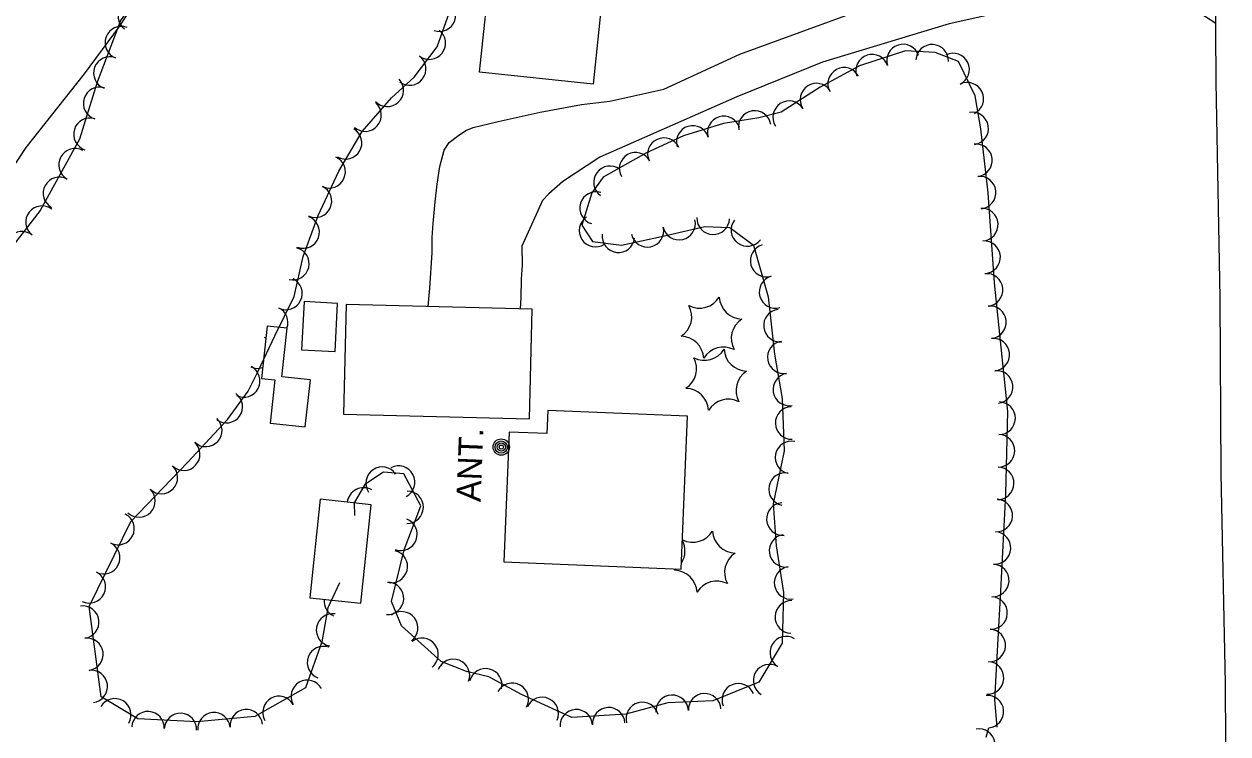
# Model space of a CAD drawing. Extents: x 296487 to 298842, y 31545 to 32791.
# Drawn here: x 297435.1 to 297732.5, y 31860.3 to 32035.7 of the extents above; entities that cross this region are included whole.
import ezdxf

# ---------------------------------------------------------------- set-up
doc = ezdxf.new("R2010")
doc.units = 0
for name, color, linetype in [('Level 11', 7, 'Continuous'), ('Level 12', 7, 'Continuous'), ('Level 14', 7, 'Continuous'), ('Level 17', 7, 'Continuous'), ('Level 18', 7, 'Continuous')]:
    doc.layers.add(name, color=color, linetype=linetype)

msp = doc.modelspace()

# ---------------------------------------------------------------- linework, layer by layer
at = {"layer": 'Level 11'}
msp.add_lwpolyline([(297732.45, 31749.54), (297732.24, 31791.84), (297732.13, 31829.29), (297731.83, 31872.75), (297730.81, 31924.68), (297730.53, 31968.01), (297729.53, 32021.42), (297729.12, 32084.97), (297728.52, 32147.82), (297727.87, 32212.59), (297727.19, 32277.97), (297726.38, 32352.97), (297725.93, 32414.91), (297724.99, 32486.15), (297724.55, 32554.59), (297723.53, 32621.52), (297723.38, 32689.57), (297722.58, 32747.62), (297722.25, 32760.6)], dxfattribs=at)
at = {"layer": 'Level 12'}
for points in [[(297547.6, 32023.83), (297550.48, 32050.93), (297578.49, 32047.96), (297575.62, 32020.86)], [(297512.53, 31966.69), (297504.25, 31967.13), (297503.62, 31955.23), (297511.9, 31954.79)], [(297560.58, 31965.29), (297514.62, 31966.43), (297513.95, 31939.3), (297559.91, 31938.16)], [(297505.79, 31947.78), (297498.77, 31948.53), (297500.06, 31960.54), (297495.1, 31961.07), (297493.71, 31948.12), (297496.98, 31947.77), (297495.84, 31937.1), (297504.54, 31936.17)], [(297553.6, 31902.79), (297597.41, 31901.02), (297598.94, 31938.83), (297564.47, 31940.22), (297564.23, 31934.5), (297554.9, 31934.87)], [(297520.83, 31916.93), (297508.24, 31918.27), (297505.64, 31893.94), (297518.23, 31892.59)]]:
    msp.add_lwpolyline(points, close=True, dxfattribs=at)
at = {"layer": 'Level 14'}
for centre, radius in [((297552.94, 31931.18), 2.02), ((297552.93, 31931.17), 1.52), ((297552.97, 31931.18), 1.01), ((297552.96, 31931.18), 0.502)]:
    msp.add_circle(centre, radius, dxfattribs=at)
at = {"layer": 'Level 17'}
for points in [[(297623.99, 32250.43), (297610.13, 32233.83), (297591.62, 32212.39), (297578.2, 32195.81), (297559.31, 32173.69), (297545.59, 32153.8), (297535.31, 32140.44), (297511.71, 32112.03), (297495.92, 32087.9), (297480.91, 32066.68), (297468.73, 32050.81), (297458.54, 32035.07), (297449.94, 32023.36), (297435.5, 32005.16), (297419.75, 31981.41), (297405.85, 31956.85), (297394.34, 31937.67), (297382.2, 31916.55), (297361.04, 31874.71), (297352.86, 31857.17), (297348.71, 31848.4), (297345.52, 31842.04), (297344.4, 31839.03)], [(297729.44, 32035.81), (297724.4, 32039.11), (297721.87, 32040.79), (297718.97, 32042.8), (297715.9, 32043.7), (297713, 32044.12), (297711.06, 32044.15), (297709.77, 32044.05), (297688.43, 32041.23), (297663.57, 32035.71), (297632.32, 32026.27), (297611.12, 32017.74), (297577.29, 32002.8), (297568.14, 31996.83), (297564.66, 31993.74), (297563.14, 31992.11), (297558.04, 31980.8), (297558.08, 31976.14), (297557.89, 31972.64), (297557.78, 31968.11), (297557.58, 31965.36)], [(297534.93, 31965.92), (297535.29, 31970.41), (297535.84, 31979.17), (297535.88, 31982.92), (297536.12, 31986.45), (297536.64, 31991.78), (297537.15, 31996.11), (297537.77, 32000.47), (297538.86, 32004.55), (297540.07, 32006.43), (297542.11, 32008.03), (297544.23, 32009.37), (297545.98, 32010.17), (297552.18, 32011.64), (297562.58, 32013.89), (297572.81, 32015.8), (297579.78, 32016.64), (297593.08, 32019.57), (297611.92, 32028.26), (297648.67, 32041.76)]]:
    msp.add_lwpolyline(points, dxfattribs=at)
at = {"layer": 'Level 18'}
for points in [[(297625.12, 32240.7), (297616.41, 32235.22), (297611.15, 32232.85), (297605.92, 32227.61), (297598.25, 32212.26), (297590.54, 32195.59), (297580.41, 32181.49), (297570.67, 32169.45), (297556.76, 32152.58), (297535.87, 32128.56), (297522.19, 32111.09), (297509.57, 32094.44), (297500.55, 32082.07), (297485.94, 32065.55), (297469.04, 32050.05), (297458.99, 32036.76), (297453.15, 32021.32), (297448.73, 32007.23), (297439.07, 31989.61), (297427.97, 31975.39)], [(297512.96, 31897.65), (297510.08, 31891.48), (297508.63, 31883.02), (297504.56, 31871.72), (297492.07, 31864.64), (297477.75, 31863.3), (297463.19, 31864.07), (297454.13, 31869.44), (297451.14, 31891.8), (297461.48, 31912.76), (297475.44, 31927.33), (297485.34, 31937.98), (297490.43, 31945.03), (297492.93, 31949.9), (297496.98, 31958.65), (297501.75, 31968.41), (297504.04, 31978.23), (297507.72, 31988.36), (297512.81, 31999.32), (297518.6, 32009.17), (297525.86, 32017.44), (297531.42, 32022.57), (297537.12, 32030.07), (297541.1, 32041.21)], [(297675.48, 31862), (297674.9, 31868.74), (297675.39, 31877.8), (297676.34, 31895.69), (297677.63, 31919.54), (297678.07, 31939.98), (297674.78, 31971.76), (297673.23, 31993.97), (297671.43, 32009.79), (297670.05, 32018), (297665.92, 32026.48), (297660.15, 32028.7), (297652.8, 32029.09), (297641.45, 32025.36), (297631.7, 32020.09), (297622.13, 32013.94), (297616.56, 32012.55), (297607.84, 32011.1), (297597.97, 32008.07), (297588.79, 32003.87), (297578.14, 31997.89), (297575.31, 31994.01), (297572.88, 31985.97), (297575.5, 31981.96), (297582.67, 31981.07), (297592.54, 31983.23), (297603.21, 31985.69), (297609.43, 31985.46), (297615.23, 31981.07), (297618.85, 31968.31), (297620.48, 31954.15), (297622.35, 31943.15), (297622.84, 31930.28), (297620.15, 31917.16), (297620.86, 31906.75), (297622.67, 31895.23), (297622.32, 31882.76), (297616.54, 31873.07), (297605.25, 31868.48), (297594.08, 31867.96), (297583.69, 31865.19), (297570.36, 31864.36), (297557.91, 31870.01), (297549.84, 31874.41), (297544.34, 31875.76), (297538.14, 31878.18), (297528.31, 31887.01), (297525.82, 31893.01), (297528.96, 31905.79), (297533.07, 31916.62), (297528.88, 31924.54), (297523.83, 31924.99), (297519.28, 31921.94), (297516.64, 31917.42), (297516.72, 31914.3)], [(297672.71, 31859.47), (297673.38, 31861.82)]]:
    msp.add_lwpolyline(points, dxfattribs=at)
for centre, radius, start, end in [((297462.31, 32037.69), 4.01, 52.906, 232.8907), ((297537.69, 32037.89), 4.01, 250.3652, 70.3499), ((297459.08, 32031.09), 4.01, 69.292, 249.2767), ((297535.17, 32030.97), 4.01, 232.7376, 52.7223), ((297652.21, 32026.68), 4.02, 18.1955, 198.1802), ((297659.4, 32026.63), 4.02, 356.922, 176.9067), ((297664.56, 32024.47), 4.02, 295.9288, 115.9135), ((297456.25, 32023.6), 4.01, 69.292, 249.2767), ((297530.32, 32024.59), 4.01, 232.7376, 52.7223), ((297644.57, 32024.17), 4.02, 18.1955, 198.1802), ((297637.66, 32020.92), 4.02, 28.4036, 208.3883), ((297453.71, 32016.12), 4.01, 72.5902, 252.5749), ((297524.8, 32019.32), 4.01, 222.7158, 42.7004), ((297630.82, 32017.03), 4.02, 32.7374, 212.7221), ((297668.08, 32017.24), 4.02, 295.9288, 115.9135), ((297624.06, 32012.68), 4.02, 32.7374, 212.7221), ((297519.32, 32013.17), 4.01, 228.739, 48.7237), ((297615.57, 32010.25), 4.02, 9.4529, 189.4376), ((297669.28, 32009.9), 4.02, 279.5944, 99.5791), ((297451.32, 32008.48), 4.01, 72.5902, 252.5749), ((297600.25, 32006.57), 4.02, 17.0761, 197.0608), ((297607.93, 32008.93), 4.02, 17.0761, 197.0608), ((297514.5, 32006.33), 4.01, 239.5454, 59.5301), ((297593.12, 32003.54), 4.02, 24.5943, 204.579), ((297447.66, 32000.92), 4.01, 61.2691, 241.2538), ((297670.2, 32002.03), 4.02, 276.4937, 96.4784), ((297510.43, 31999.19), 4.01, 245.0987, 65.0834), ((297586.12, 31999.96), 4.02, 29.3112, 209.2959), ((297579.8, 31996.6), 4.02, 53.9154, 233.9001), ((297443.8, 31993.89), 4.01, 61.2691, 241.2538), ((297507.06, 31991.92), 4.01, 245.0987, 65.0834), ((297671.11, 31994.05), 4.02, 276.4937, 96.4784), ((297576.37, 31990.24), 4.02, 73.1791, 253.1638), ((297439.5, 31986.76), 4.01, 52.0486, 232.0333), ((297671.67, 31986.12), 4.02, 273.9996, 93.9843), ((297504.02, 31984.32), 4.01, 250.0682, 70.0528), ((297576.24, 31984.66), 4.02, 123.1839, 303.1685), ((297596.87, 31986.39), 4.02, 192.9568, 12.9415), ((297605.3, 31987.72), 4.02, 177.9356, 357.9203), ((297613.75, 31984.83), 4.02, 142.8478, 322.8325), ((297434.57, 31980.44), 4.01, 52.0486, 232.0333), ((297581.89, 31983.28), 4.02, 172.9426, 352.9273), ((297589.05, 31984.62), 4.02, 192.3992, 12.3839), ((297618.5, 31977.24), 4.02, 105.8569, 285.8416), ((297672.23, 31978.1), 4.02, 273.9996, 93.9843), ((297501.48, 31976.47), 4.01, 256.8781, 76.8627), ((297499.77, 31969.12), 4.01, 243.9806, 63.9653), ((297620.7, 31969.5), 4.02, 105.8569, 285.8416), ((297672.85, 31970.02), 4.02, 275.9174, 95.902), ((297594.28, 31963.38), 5.72, 302.8816, 28.6465), ((297601.91, 31971.22), 5.72, 242.8816, 328.6465), ((297612.52, 31968.53), 5.72, 182.8816, 268.6465), ((297673.67, 31962.03), 4.02, 275.9174, 95.902), ((297496.25, 31961.92), 4.01, 339.8448, 63.9653), ((297615.49, 31958), 5.72, 122.8816, 208.6465), ((297621.78, 31961.2), 4.02, 96.5515, 276.5362), ((297492.81, 31954.63), 4.01, 60.6179, 65.1342), ((297597.25, 31952.85), 5.72, 2.8816, 88.6465), ((297622.75, 31953.34), 4.02, 99.6794, 279.6641), ((297674.5, 31954.03), 4.02, 275.9174, 95.902), ((297603.09, 31958.34), 5.72, 242.8816, 328.6465), ((297607.86, 31950.16), 5.72, 62.8816, 148.6465), ((297613.7, 31955.65), 5.72, 182.8816, 268.6465), ((297489.34, 31947.51), 4.01, 242.816, 62.8007), ((297492.81, 31954.63), 4.01, 245.1495, 287.1692), ((297595.46, 31950.5), 5.72, 302.8816, 28.6465), ((297616.67, 31945.12), 5.72, 122.8816, 208.6465), ((297624.1, 31945.42), 4.02, 99.6794, 279.6641), ((297675.33, 31946.04), 4.02, 275.9174, 95.902), ((297598.43, 31939.97), 5.72, 2.8816, 88.6465), ((297485.04, 31941.14), 4.01, 234.1911, 54.1758), ((297609.04, 31937.28), 5.72, 62.8816, 148.6465), ((297675.93, 31938.3), 4.02, 268.7745, 88.7592), ((297624.68, 31937.14), 4.02, 92.1974, 272.1821), ((297479.97, 31935.29), 4.01, 227.0925, 47.0771), ((297675.76, 31930.26), 4.02, 268.7745, 88.7592), ((297474.52, 31929.42), 4.01, 227.0925, 47.0771), ((297624.65, 31928.63), 4.02, 78.4277, 258.4124), ((297469, 31923.64), 4.01, 226.2347, 46.2193), ((297523.52, 31922.25), 4.02, 33.8517, 213.8364), ((297527.58, 31922.51), 4.02, 297.9229, 117.9076), ((297623.04, 31920.76), 4.02, 78.4277, 258.4124), ((297675.58, 31922.22), 4.02, 268.7745, 88.7592), ((297518.91, 31917.13), 4.02, 59.7528, 173.8599), ((297463.46, 31917.86), 4.01, 226.2347, 46.2193), ((297529.68, 31916.29), 4.02, 269.2317, 89.2164), ((297675.24, 31914.26), 4.02, 266.9086, 86.8933), ((297622.52, 31913.38), 4.02, 93.9058, 273.8905), ((297458.29, 31911.03), 4.01, 243.7485, 63.7332), ((297528.16, 31909.61), 4.02, 249.2317, 69.2164), ((297600.25, 31913.4), 5.72, 243.6326, 328.6465), ((297610.85, 31910.71), 5.72, 182.8816, 268.6465), ((297623.18, 31905.56), 4.02, 98.9177, 278.9024), ((297674.8, 31906.24), 4.02, 266.9086, 86.8933), ((297454.74, 31903.84), 4.01, 243.7485, 63.7332), ((297592.62, 31905.56), 5.72, 328.0767, 27.2974), ((297525.78, 31901.68), 4.02, 256.171, 76.1557), ((297613.83, 31900.18), 5.72, 122.8816, 208.6465), ((297592.62, 31905.56), 5.72, 302.8816, 308.3192), ((297595.59, 31895.03), 5.72, 2.8816, 88.6465), ((297624.42, 31897.62), 4.02, 98.9177, 278.9024), ((297674.37, 31898.21), 4.02, 266.9086, 86.8933), ((297451.2, 31896.65), 4.01, 243.7485, 63.7332), ((297524.83, 31893.79), 4.02, 266.171, 86.1557), ((297606.19, 31892.34), 5.72, 62.8816, 148.6465), ((297449.55, 31887.92), 4.01, 277.6077, 97.5924), ((297513.17, 31893.13), 4.01, 173.8697, 244.917), ((297624.6, 31889.22), 4.02, 88.3994, 268.3841), ((297673.94, 31890.19), 4.02, 266.9616, 86.9463), ((297511.26, 31885.99), 4.01, 80.2842, 260.2689), ((297528.32, 31886.51), 4.02, 308.033, 128.0177), ((297673.51, 31882.16), 4.02, 266.9616, 86.9463), ((297450.61, 31879.97), 4.01, 277.6077, 97.5924), ((297533.39, 31879.96), 4.02, 308.033, 128.0177), ((297623.35, 31880.38), 4.02, 59.2216, 239.2062), ((297509.03, 31877.94), 4.01, 70.2161, 250.2008), ((297541.13, 31874.76), 4.02, 338.7451, 158.7298), ((297619.24, 31873.48), 4.02, 59.2216, 239.2062), ((297673.08, 31874.14), 4.02, 266.9339, 86.9185), ((297451.67, 31872.03), 4.01, 277.6077, 97.5924), ((297505.03, 31869.58), 4.01, 29.5517, 209.5363), ((297549.09, 31872.43), 4.02, 346.2144, 166.1991), ((297555.66, 31868.84), 4.02, 331.3689, 151.3535), ((297611.5, 31868.75), 4.02, 22.1153, 202.1), ((297457.47, 31865.02), 4.01, 329.3918, 149.3765), ((297498.06, 31865.62), 4.01, 29.5517, 209.5363), ((297563.07, 31865.35), 4.02, 335.6057, 155.5903), ((297587.81, 31864.11), 4.02, 14.88, 194.8647), ((297595.17, 31865.9), 4.02, 2.6842, 182.6689), ((297603.2, 31866.28), 4.02, 2.6842, 182.6689), ((297673.04, 31865.82), 4.02, 274.8783, 94.863), ((297465.68, 31861.84), 4.01, 356.9515, 176.9362), ((297473.68, 31861.41), 4.01, 356.9515, 176.9362), ((297481.98, 31861.59), 4.01, 5.3539, 185.3386), ((297489.96, 31862.33), 4.01, 5.3539, 185.3386), ((297571.48, 31862.32), 4.02, 3.6006, 183.5853), ((297579.5, 31862.82), 4.02, 3.6006, 183.5853), ((297670.94, 31857.62), 3.96, 279.9695, 99.9541)]:
    msp.add_arc(centre, radius, start, end, dxfattribs=at)

# ---------------------------------------------------------------- texts
at = {"layer": 'Level 14'}
msp.add_text('ANT.', height=6, rotation=87.6703, dxfattribs=at).set_placement((297547.82, 31917.56))

doc.saveas('drawing.dxf')
